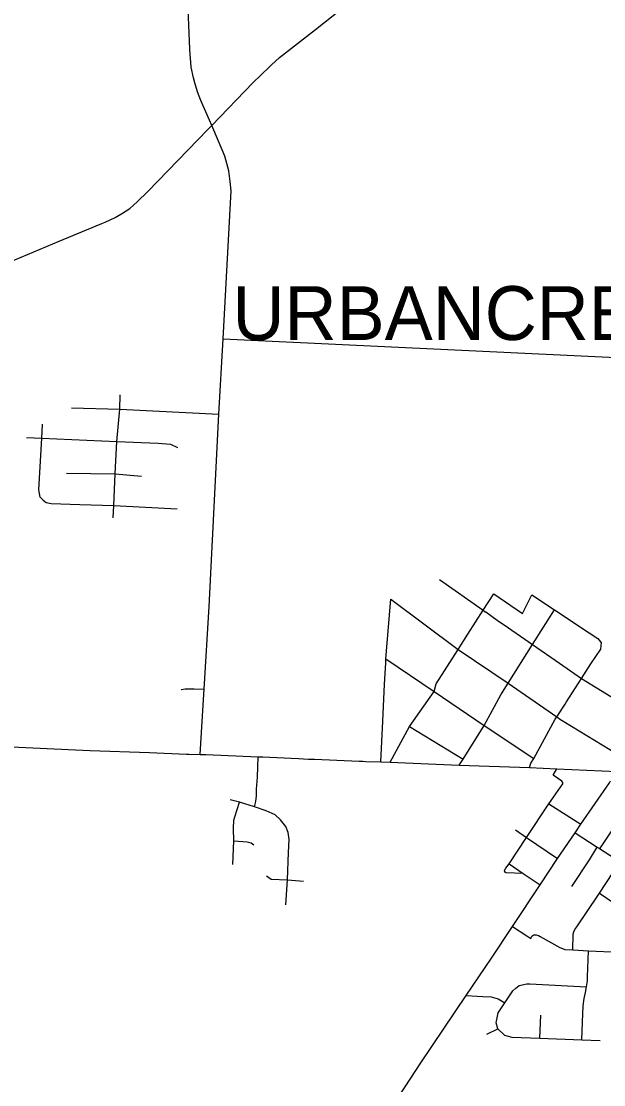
# Model space of a CAD drawing. Extents: x 1755200 to 1902939, y 644115 to 788070.
# Drawn here: x 1796306 to 1801711, y 683051 to 692927 of the extents above; entities that cross this region are included whole.
import ezdxf

# ---------------------------------------------------------------- set-up
doc = ezdxf.new("R2010")
doc.units = 0
for name, color, linetype in [('GM_X_City_Street', 7, 'Continuous'), ('GM_X_Corporation_Text', 7, 'Continuous'), ('GM_X_County_Road', 7, 'Continuous'), ('GM_X_US_Route', 7, 'Continuous')]:
    doc.layers.add(name, color=color, linetype=linetype)

msp = doc.modelspace()

# ---------------------------------------------------------------- linework, layer by layer
at = {"layer": 'GM_X_City_Street'}
for points in [[(1798052.6, 692007.4), (1797971, 692191.9), (1797940.8, 692270.7), (1797917, 692354.9), (1797904, 692401.4), (1797883.5, 692500.7), (1797878.1, 692547.2), (1797872.7, 692618.4), (1797868.4, 692670.3), (1797846.8, 693188.6), (1797845.8, 693384.9)], [(1798073.7, 691959.6), (1798455.1, 692356.1), (1798608, 692504.8), (1798626.4, 692521.9)], [(1798036.8, 691921.5), (1798073.7, 691959.6)], [(1798050.5, 687492.9), (1798139.3, 689277), (1798180.6, 689978.2), (1798254.2, 691351.2), (1798245.6, 691438.5), (1798230.6, 691536.6), (1798193.3, 691675.3), (1798135.8, 691812.1), (1798073.7, 691959.6), (1798052.6, 692007.4)], [(1794896.2, 690150.3), (1794967.3, 690181.6), (1795830, 690539.4), (1796658.5, 690885.2), (1796910.2, 690989.6), (1797052.8, 691047.3)], [(1798180.6, 689978.2), (1801761.2, 689806.4), (1802470.7, 689765.2), (1803037.9, 689733), (1803248.3, 689713.4), (1803388.4, 689680.3), (1803480.3, 689647.5), (1803614.3, 689592.4), (1803795.9, 689472.7), (1804014.2, 689335), (1804041.2, 689318)], [(1797158.7, 688314.5), (1797164.8, 688429), (1797177.3, 688723.5), (1797191.4, 689022.8), (1797219.1, 689324.9), (1797222.5, 689458.6)], [(1796770.5, 689337.9), (1797219.1, 689324.9), (1798139.3, 689277)], [(1796507.6, 688480.8), (1796479.7, 688508.7), (1796467.4, 688575.7), (1796496.3, 689056.3), (1796503.9, 689184.4)], [(1796354.2, 689062.2), (1796496.3, 689056.3), (1797191.4, 689022.8), (1797575.1, 689007.5), (1797690.2, 688998.5), (1797755.5, 688969.1)], [(1796724.9, 688731.2), (1797177.3, 688723.5)], [(1797177.3, 688723.5), (1797421.6, 688703.6)], [(1796507.6, 688480.8), (1796535.5, 688458.3), (1796582.7, 688448.6), (1796848.7, 688437.9), (1797164.8, 688429), (1797752.9, 688399.9)], [(1800185.6, 687741.5), (1800592, 687457.6), (1800611.6, 687443.9), (1800615.3, 687441.4)], [(1799728.2, 686047.4), (1799908.8, 686377.2), (1800138.4, 686702.1), (1800156, 686773.4), (1800358.6, 687092.3), (1800448.9, 687234.2), (1800592, 687457.6), (1800689.7, 687610), (1800958.1, 687425.5), (1801044.2, 687600.1)], [(1801044.2, 687600.1), (1801254, 687460.7), (1801574.7, 687247.5), (1801575.9, 687246.8)], [(1797967, 686118.2), (1798001.3, 686677.1), (1798002.7, 686724), (1798050.5, 687491.8), (1798050.5, 687492.9)], [(1799687.3, 686966.6), (1799689.6, 687004.7), (1799735.2, 687558.8)], [(1799735.2, 687558.8), (1800358.6, 687092.3), (1800824.5, 686779.1), (1801275.4, 686467.1), (1801309.4, 686443.6), (1801341.2, 686424.2)], [(1800370.2, 686017.6), (1800405.6, 686074.7), (1800602.5, 686385.5), (1800756.9, 686671.8), (1800824.5, 686779.1), (1801050.8, 687138.2), (1801254, 687460.7)], [(1800615.3, 687441.4), (1800722.3, 687366.5), (1800781.9, 687325.2), (1800787.2, 687321.5)], [(1800787.2, 687321.5), (1801050.8, 687138.2), (1801300.5, 686964.5), (1801505, 686824.7), (1802143.9, 686428.6)], [(1801575.9, 687246.8), (1801656.3, 687193.3), (1801681.7, 687164.7), (1801689.6, 687158.5)], [(1801364.6, 686606.6), (1801505, 686824.7), (1801591, 686958.1), (1801684.2, 687096.4), (1801689.6, 687158.5)], [(1799689.6, 687004.7), (1800138.4, 686702.1), (1800602.5, 686385.5), (1801063, 686080.5)], [(1799660.1, 686427.3), (1799675.6, 686769.8), (1799687.3, 686966.6)], [(1797790.9, 686720.2), (1797793.2, 686720.6), (1797827.9, 686726.8), (1797853.6, 686728.1), (1797911.4, 686728.1), (1798002.7, 686724)], [(1801277.4, 686470.3), (1801327.3, 686548.7), (1801351.5, 686586.4), (1801364.6, 686606.6)], [(1799643.1, 686049.6), (1799660.1, 686427.3)], [(1801021.8, 685997), (1801032.7, 686037), (1801063, 686080.5), (1801261.4, 686445.1), (1801275.4, 686467.1), (1801277.4, 686470.3)], [(1801341.2, 686424.2), (1801910.7, 686077.6), (1802137.1, 685921), (1802348.6, 685780.4), (1802526.6, 685622.7), (1802742.5, 685480.3), (1802953.6, 685341.1), (1802991.3, 685328.3), (1803027.1, 685315.4), (1803131.2, 685309.1), (1803466.4, 685293.9), (1803483.5, 685293.1), (1803502.1, 685292.2)], [(1799908.8, 686377.2), (1800405.6, 686074.7)], [(1797859.8, 686120.1), (1797967, 686118.2), (1798018.8, 686116.1)], [(1802286.2, 686159), (1802260.1, 686123.5), (1802137.1, 685921), (1801968.7, 685688.5), (1801874.6, 685548.1), (1801682.7, 685261.5), (1801670.7, 685243.6)], [(1798471.4, 685631.7), (1798481.1, 685680.2), (1798489.7, 685732.9), (1798488.7, 685794.3), (1798498.9, 685907.6), (1798505.4, 686096)], [(1798548.6, 686094.4), (1798676.2, 686089.6), (1798879, 686079.1), (1798972.4, 686075.3)], [(1798972.4, 686075.3), (1799025.4, 686073.2)], [(1799502.3, 686053.7), (1799643.1, 686049.6), (1799728.2, 686047.4), (1800370.2, 686017.6), (1801021.8, 685997), (1801275.1, 685985), (1801833.5, 685961)], [(1800963.6, 685012.6), (1800806, 685019.2), (1800797.6, 685023), (1800791.6, 685030), (1800789.8, 685032.8), (1800789.2, 685036.2), (1800790, 685039.5), (1800803.7, 685060.8), (1800833, 685103.1), (1800995, 685345.3), (1801202.2, 685660), (1801330.5, 685844.9), (1801332.2, 685858.7), (1801320.8, 685870.1), (1801240.2, 685924.4), (1801275.1, 685985)], [(1798761.4, 684722.3), (1798775.2, 684953.2), (1798786.7, 685207), (1798791.2, 685328.9), (1798781.1, 685393.1), (1798759.2, 685449.8), (1798709.7, 685509.4), (1798661.1, 685556.1), (1798578.7, 685593.7), (1798471.4, 685631.7), (1798331.3, 685673.5), (1798244.3, 685695.4)], [(1798267.7, 685096.1), (1798279.1, 685315.2), (1798276.4, 685429.7), (1798278.2, 685506.7), (1798286.7, 685539.2), (1798331.3, 685673.5)], [(1801202.2, 685660), (1801496.7, 685469.7)], [(1800890.4, 685419.4), (1800995, 685345.3), (1801283.2, 685152.6)], [(1798279.1, 685315.2), (1798401, 685306), (1798437.6, 685296.8), (1798465.1, 685278.5)], [(1801445.1, 685389.2), (1801648.6, 685256.3), (1801670.7, 685243.6), (1801809.7, 685153.6)], [(1801415.4, 684892.6), (1801577.2, 685138.4), (1801648.6, 685256.3)], [(1801657.7, 684812.2), (1801670, 684830.6), (1801861.6, 685118.6)], [(1800833, 685103.1), (1800963.6, 685012.6), (1801120.4, 684906.4)], [(1798581, 684991.7), (1798624.9, 684958.7), (1798775.2, 684953.2), (1798925.8, 684941.4)], [(1801670, 684830.6), (1801867.2, 684697.3), (1801932, 684654.6), (1801949.5, 684644.8), (1801969.2, 684640.9), (1802189.4, 684631.6), (1802195.1, 684631.4)], [(1801422.6, 684302.4), (1801428.4, 684447.6), (1801432, 684471.4), (1801442.6, 684493), (1801460.8, 684517), (1801657.7, 684812.2)], [(1800865.4, 684519.6), (1800996.4, 684433.8), (1801033.3, 684410), (1801044.8, 684430), (1801063.2, 684442), (1801074.5, 684442.1)], [(1801074.5, 684442.1), (1801085.2, 684442.2), (1801105.4, 684436.6), (1801119.6, 684428.8), (1801302.2, 684326), (1801343.4, 684308.4), (1801349.3, 684308)], [(1801349.3, 684308), (1801422.6, 684302.4), (1801570.8, 684294.4), (1801850.4, 684281.4), (1801850.4, 684281.4), (1802174.2, 684265.9), (1802785.4, 684232.4)], [(1801508.4, 683468.2), (1801514, 683632.2), (1801520.4, 683784.4), (1801530, 683852.4), (1801542.2, 683908), (1801551.6, 683960.6), (1801560.2, 684017), (1801561.6, 684054), (1801570.8, 684294.4)], [(1800727, 683569.6), (1800711.4, 683625.4), (1800732.6, 683719.6), (1800793.2, 683811), (1800867.4, 683922.6), (1800894.1, 683946.4)], [(1800894.1, 683946.4), (1800924.6, 683973.2), (1800996.4, 683988), (1801023.8, 683987), (1801551.6, 683960.6)], [(1800433.6, 683879.6), (1800536, 683874.5), (1800588.1, 683871.3), (1800666.8, 683867.8), (1800732.6, 683847.1), (1800793.2, 683811)], [(1801118.8, 683481.7), (1801125.8, 683697.1)], [(1800625.8, 683520), (1800727, 683569.6)], [(1800727, 683569.6), (1800788.4, 683509.7), (1800858.2, 683491.9), (1801118.8, 683481.7), (1801508.4, 683468.2), (1801678.3, 683461.5)]]:
    msp.add_lwpolyline(points, dxfattribs=at)
at = {"layer": 'GM_X_County_Road'}
for points in [[(1798626.4, 692521.9), (1798700.6, 692590.9), (1799036.7, 692849), (1799349.1, 693096.8), (1799503.1, 693221.7), (1799684.1, 693381.2), (1799969.5, 693661.9), (1800111.7, 693793.3), (1800279.2, 693941.2), (1800585.2, 694168.6), (1800986.2, 694447.1), (1801199.6, 694619.8), (1801300, 694689.1), (1801318.6, 694702)], [(1797052.8, 691047.3), (1797085.6, 691060.6), (1797177.2, 691104.3), (1797244.8, 691143.6), (1797314.2, 691189), (1797380.9, 691249.8), (1797479.3, 691345.6), (1798036.8, 691921.5)], [(1794839.7, 686241.7), (1795948, 686200.5), (1796942.7, 686155.9), (1797494.9, 686135.3), (1797837.8, 686120.4), (1797859.8, 686120.1)], [(1798018.8, 686116.1), (1798505.4, 686096), (1798548.6, 686094.4)], [(1799025.4, 686073.2), (1799441.9, 686056.3), (1799449.3, 686055.9)], [(1799449.3, 686055.9), (1799476.3, 686054.5), (1799502.3, 686053.7)]]:
    msp.add_lwpolyline(points, dxfattribs=at)
at = {"layer": 'GM_X_US_Route'}
for points in [[(1800668.1, 684227.3), (1800865.4, 684519.6), (1801120.4, 684906.4), (1801283.2, 685152.6), (1801445.1, 685389.2), (1801496.7, 685469.7), (1801763.2, 685855.8), (1801774.4, 685872.5)], [(1799919.8, 683110.8), (1800013.8, 683254.6), (1800433.6, 683879.6), (1800668.1, 684227.3)], [(1799534.5, 682537.3), (1799802.2, 682930.7), (1799919.8, 683110.8)]]:
    msp.add_lwpolyline(points, dxfattribs=at)

# ---------------------------------------------------------------- texts
at = {"layer": 'GM_X_Corporation_Text'}
msp.add_text('URBANCREST', height=500, rotation=0.00001, dxfattribs=at).set_placement((1798266.2, 689966.8))

doc.saveas('drawing.dxf')
